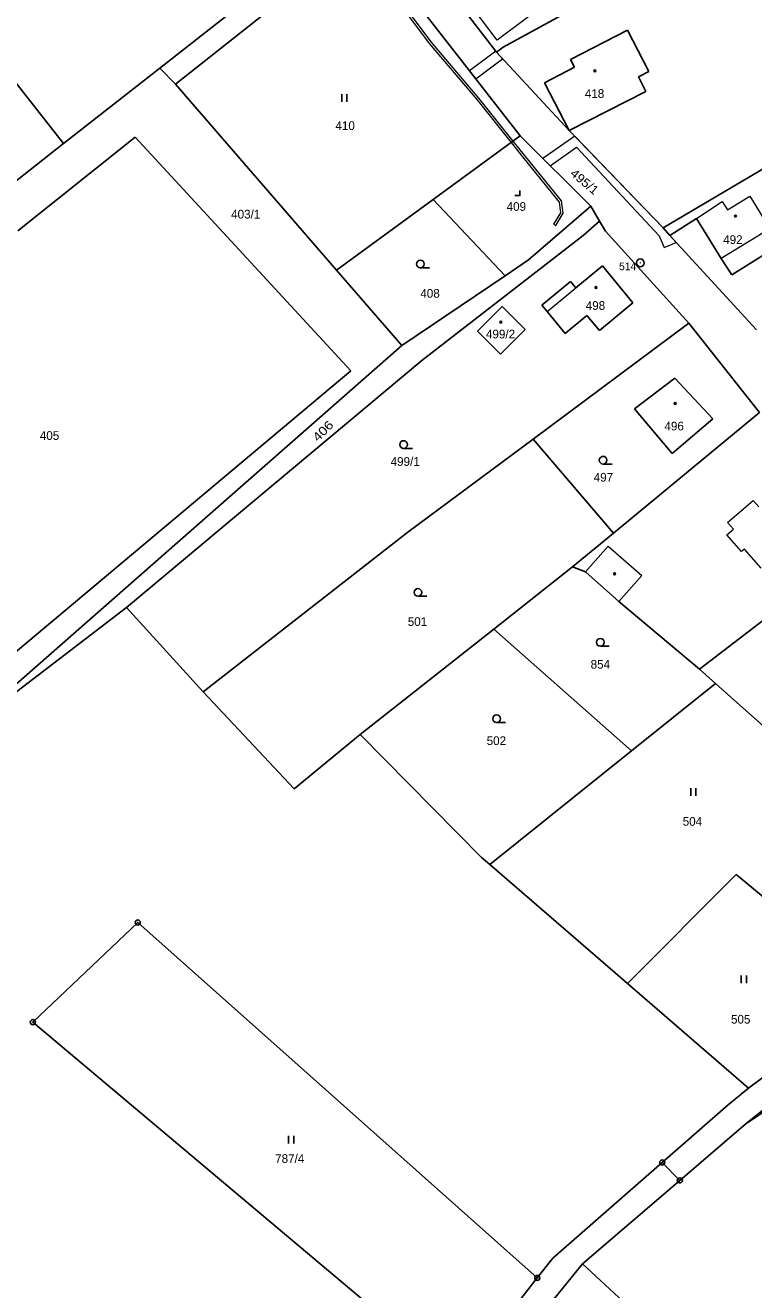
# Model space of a CAD drawing. Extents: x -727701 to -724405, y -960481 to -957284.
# Drawn here: x -726949 to -726806.8, y -958649.2 to -958402.3 of the extents above; entities that cross this region are included whole.
import ezdxf
from ezdxf.enums import TextEntityAlignment as Align

# ---------------------------------------------------------------- set-up
doc = ezdxf.new("R2010")
doc.units = 0
doc.header["$LTSCALE"] = 0.68
for name, color, linetype, lineweight in [('1', 7, 'Continuous', 25), ('13', 7, 'Continuous', 13), ('3', 7, 'Continuous', 25), ('4', 7, 'Continuous', 13), ('5', 7, 'Continuous', 25), ('8', 7, 'Continuous', 25)]:
    doc.layers.add(name, color=color, linetype=linetype, lineweight=lineweight)
doc.layers.add('2', color=7, linetype='Continuous')

msp = doc.modelspace()

# ---------------------------------------------------------------- linework, layer by layer
at = {"layer": '1'}
for p, q in [((-726885.47, -958381.37), (-726922.74, -958410.62)), ((-726974.6, -958383.32), (-726941.54, -958425.38)), ((-726919.69, -958413.75), (-726882.93, -958384.54)), ((-726882.93, -958384.54), (-726852.38, -958423.88)), ((-726869.9, -958390.7), (-726857, -958407.5)), ((-726855.71, -958406.56), (-726838.78, -958397.26)), ((-726842.54, -958408.92), (-726831.41, -958403.2)), ((-726827.24, -958411.31), (-726831.41, -958403.2)), ((-726857, -958407.5), (-726855.71, -958406.56)), ((-726857, -958407.5), (-726842.78, -958422.8)), ((-726841.75, -958410.45), (-726842.54, -958408.92)), ((-726922.74, -958410.62), (-726941.54, -958425.38)), ((-726919.69, -958413.75), (-726922.74, -958410.62)), ((-726847.61, -958413.5), (-726841.75, -958410.45)), ((-726829.26, -958412.35), (-726827.24, -958411.31)), ((-726827.81, -958415.17), (-726829.26, -958412.35)), ((-726888.22, -958450.06), (-726919.69, -958413.75)), ((-726842.78, -958422.8), (-726847.61, -958413.5)), ((-726842.78, -958422.8), (-726827.81, -958415.17)), ((-726950.5, -958442.38), (-726927.59, -958424.09)), ((-726927.59, -958424.09), (-726885.45, -958469.72)), ((-726869.34, -958436.27), (-726852.38, -958423.88)), ((-726852.38, -958423.88), (-726838.54, -958437.62)), ((-726842.78, -958422.8), (-726824.46, -958441.82)), ((-726941.54, -958425.38), (-726955.38, -958436.25)), ((-726824.46, -958441.82), (-726801.69, -958428.42)), ((-726888.22, -958450.06), (-726869.34, -958436.27)), ((-726869.34, -958436.27), (-726855.32, -958451.17)), ((-726850.77, -958448.09), (-726838.54, -958437.62)), ((-726838.54, -958437.62), (-726836.88, -958440.5)), ((-726840.04, -958443.34), (-726836.88, -958440.5)), ((-726836.88, -958440.5), (-726835.73, -958442.5)), ((-726824.46, -958441.82), (-726823.11, -958443.32)), ((-726823.11, -958443.32), (-726817.95, -958439.97)), ((-726813.08, -958447.79), (-726817.95, -958439.97)), ((-726811.04, -958451.01), (-726794.03, -958440.35)), ((-726871.56, -958467.73), (-726840.04, -958443.34)), ((-726835.73, -958442.5), (-726819.45, -958460.45)), ((-726823.11, -958443.32), (-726806.2, -958461.75)), ((-726855.32, -958451.17), (-726850.77, -958448.09)), ((-726841.52, -958453.57), (-726836.29, -958449.26)), ((-726836.29, -958449.26), (-726830.34, -958456.48)), ((-726813.08, -958447.79), (-726811.04, -958451.01)), ((-726875.45, -958464.8), (-726888.22, -958450.06)), ((-726875.45, -958464.8), (-726855.32, -958451.17)), ((-726848.15, -958456.92), (-726842.56, -958452.31)), ((-726842.56, -958452.31), (-726841.52, -958453.57)), ((-726847.11, -958458.18), (-726848.15, -958456.92)), ((-726830.34, -958456.48), (-726836.9, -958461.88)), ((-726860.67, -958462.03), (-726855.87, -958457.21)), ((-726855.87, -958457.21), (-726851.37, -958461.7)), ((-726843.59, -958462.45), (-726847.11, -958458.18)), ((-726839.32, -958458.94), (-726843.59, -958462.45)), ((-726836.9, -958461.88), (-726839.32, -958458.94)), ((-726851.37, -958461.7), (-726856.18, -958466.52)), ((-726849.85, -958483.1), (-726819.45, -958460.45)), ((-726819.45, -958460.45), (-726805.6, -958477.88)), ((-726856.18, -958466.52), (-726860.67, -958462.03)), ((-726875.45, -958464.8), (-726958.11, -958537.36)), ((-726871.56, -958467.73), (-726929.23, -958515.98)), ((-726885.45, -958469.72), (-726961.43, -958533.5)), ((-726830.04, -958477.2), (-726822.14, -958471.2)), ((-726822.14, -958471.2), (-726814.77, -958479.09)), ((-726805.6, -958477.88), (-726834.13, -958501.42)), ((-726822.7, -958485.92), (-726830.04, -958477.2)), ((-726814.77, -958479.09), (-726822.7, -958485.92)), ((-726874.3, -958501.25), (-726849.85, -958483.1)), ((-726849.85, -958483.1), (-726834.13, -958501.42)), ((-726914.29, -958532.43), (-726874.3, -958501.25)), ((-726834.13, -958501.42), (-726842.15, -958508.04)), ((-726783.4, -958501.96), (-726817.37, -958528.01)), ((-726857.54, -958520.18), (-726842.15, -958508.04)), ((-726842.15, -958508.04), (-726839.64, -958509.03)), ((-726839.64, -958509.03), (-726833.08, -958514.79)), ((-726964.44, -958542.91), (-726929.23, -958515.98)), ((-726914.29, -958532.43), (-726929.23, -958515.98)), ((-726833.08, -958514.79), (-726817.37, -958528.01)), ((-726883.62, -958540.76), (-726857.54, -958520.18)), ((-726857.54, -958520.18), (-726830.63, -958543.98)), ((-726814.19, -958530.83), (-726817.37, -958528.01)), ((-726830.63, -958543.98), (-726814.19, -958530.83)), ((-726801.26, -958542.32), (-726814.19, -958530.83)), ((-726896.5, -958551.4), (-726914.29, -958532.43)), ((-726883.62, -958540.76), (-726896.5, -958551.4)), ((-726859.96, -958564.72), (-726883.62, -958540.76)), ((-726858.32, -958566.14), (-726830.63, -958543.98)), ((-726859.96, -958564.72), (-726858.32, -958566.14)), ((-726858.32, -958566.14), (-726831.42, -958589.38)), ((-726810.2, -958568.1), (-726831.42, -958589.38)), ((-726810.2, -958568.1), (-726782.56, -958590.97)), ((-726927.06, -958577.48), (-726947.54, -958596.95)), ((-726849.02, -958646.89), (-726927.06, -958577.48)), ((-726831.42, -958589.38), (-726807.78, -958609.8)), ((-726782.56, -958590.97), (-726807.78, -958609.8)), ((-726778.4, -958592.89), (-726808.24, -958616.76)), ((-726947.54, -958596.95), (-726864.59, -958666.66)), ((-726808.24, -958616.76), (-726791.12, -958605.31)), ((-726807.78, -958609.8), (-726811.76, -958613.11)), ((-726811.76, -958613.11), (-726824.62, -958624.35)), ((-726821.18, -958627.84), (-726808.24, -958616.76)), ((-726845.96, -958643.01), (-726824.62, -958624.35)), ((-726824.62, -958624.35), (-726821.18, -958627.84)), ((-726821.18, -958627.84), (-726840.21, -958644.12)), ((-726886.94, -958701.8), (-726840.21, -958644.12)), ((-726849.02, -958646.89), (-726845.96, -958643.01)), ((-726840.21, -958644.12), (-726776.59, -958702.84)), ((-726864.59, -958666.66), (-726849.02, -958646.89))]:
    msp.add_line(p, q, dxfattribs=at)
at = {"layer": '13'}
msp.add_lwpolyline([(-726878.41, -958394.68), (-726870.15, -958405.83), (-726860.81, -958416.79), (-726854.15, -958425.18), (-726853.75, -958424.88), (-726860.42, -958416.47), (-726869.76, -958405.52), (-726878.03, -958394.36)], dxfattribs=at)
for points in [[(-726862.27, -958411.14), (-726861.05, -958412.72), (-726855.8, -958408.79), (-726857, -958407.5), (-726857.15, -958407.3)], [(-726853.75, -958424.88), (-726854.15, -958425.18), (-726851.94, -958427.97), (-726844.78, -958436.78), (-726844.48, -958438.87), (-726845.85, -958441.08), (-726845.42, -958441.34), (-726843.96, -958438.98), (-726844.31, -958436.57), (-726851.55, -958427.65)], [(-726847.93, -958428.29), (-726846.49, -958429.72), (-726841.34, -958426.1), (-726825.22, -958443.39), (-726824.27, -958445.66), (-726821.88, -958444.66), (-726823.11, -958443.32), (-726824.46, -958441.82), (-726841.71, -958423.91)]]:
    msp.add_lwpolyline(points, close=True, dxfattribs=at)
at = {"layer": '3'}
for p, q in [((-726887.201, -958417.19), (-726887.201, -958415.69)), ((-726886.2, -958417.19), (-726886.2, -958415.69)), ((-726871.853, -958449.64), (-726870.103, -958449.64)), ((-726875.143, -958484.89), (-726873.393, -958484.89)), ((-726836.173, -958487.95), (-726834.423, -958487.95)), ((-726872.343, -958513.77), (-726870.593, -958513.77)), ((-726836.703, -958523.51), (-726834.953, -958523.51)), ((-726856.973, -958538.43), (-726855.223, -958538.43)), ((-726819.041, -958552.75), (-726819.041, -958551.25)), ((-726818.04, -958552.75), (-726818.04, -958551.25)), ((-726809.181, -958589.35), (-726809.181, -958587.85)), ((-726808.18, -958589.35), (-726808.18, -958587.85)), ((-726897.591, -958620.62), (-726897.591, -958619.12)), ((-726896.59, -958620.62), (-726896.59, -958619.12))]:
    msp.add_line(p, q, dxfattribs=at)
msp.add_lwpolyline([(-726853.431, -958435.52), (-726852.43, -958435.52), (-726852.43, -958434.52)], dxfattribs=at)
for centre in [(-726871.8529, -958448.8898), (-726875.1429, -958484.1398), (-726836.1729, -958487.1998), (-726872.3429, -958513.0198), (-726836.7029, -958522.7598), (-726856.9729, -958537.6798)]:
    msp.add_circle(centre, 0.75, dxfattribs=at)
at = {"layer": '4'}
for p, q in [((-726856.84, -958405.19), (-726865.4, -958393.89)), ((-726846.05, -958397.05), (-726856.84, -958405.19)), ((-726817.95, -958439.97), (-726812.91, -958436.69)), ((-726812.91, -958436.69), (-726811.88, -958438.34)), ((-726811.88, -958438.34), (-726807.53, -958435.64)), ((-726807.53, -958435.64), (-726803.59, -958441.99)), ((-726803.59, -958441.99), (-726813.08, -958447.79)), ((-726847.11, -958458.18), (-726841.52, -958453.57)), ((-726811.86, -958499.39), (-726806.86, -958495.05)), ((-726806.86, -958495.05), (-726805.76, -958496.31)), ((-726811.98, -958501.78), (-726810.73, -958500.69)), ((-726810.73, -958500.69), (-726811.86, -958499.39)), ((-726809.11, -958505.04), (-726811.98, -958501.78)), ((-726839.64, -958509.03), (-726835.19, -958503.96)), ((-726835.19, -958503.96), (-726828.63, -958509.72)), ((-726808.55, -958504.56), (-726809.11, -958505.04)), ((-726805.3, -958508.27), (-726808.55, -958504.56)), ((-726828.63, -958509.72), (-726833.08, -958514.79))]:
    msp.add_line(p, q, dxfattribs=at)
at = {"layer": '5'}
for centre in [(-726837.7868, -958411.1592), (-726810.3168, -958439.5292), (-726837.5768, -958453.4792), (-726856.1468, -958460.2492), (-726822.0868, -958476.1192), (-726833.9268, -958509.3792)]:
    msp.add_circle(centre, 0.175, dxfattribs=at)
at = {"layer": '8'}
for centre, radius in [((-726828.89, -958448.6598), 0.75), ((-726828.89, -958448.6598), 0.03), ((-726927.06, -958577.4799), 0.5), ((-726927.06, -958577.4799), 0.0303), ((-726947.54, -958596.9499), 0.5), ((-726947.54, -958596.9499), 0.0303), ((-726824.62, -958624.3499), 0.5), ((-726824.62, -958624.3499), 0.0303), ((-726821.18, -958627.8399), 0.5), ((-726821.18, -958627.8399), 0.0303), ((-726849.02, -958646.8899), 0.5), ((-726849.02, -958646.8899), 0.0303)]:
    msp.add_circle(centre, radius, dxfattribs=at)

# ---------------------------------------------------------------- texts
at = {"layer": '2'}
for s, p in [('418', (-726839.74, -958416.455)), ('410', (-726888.45, -958422.715)), ('409', (-726855.01, -958438.505)), ('492', (-726812.72, -958444.975)), ('408', (-726871.86, -958455.465)), ('498', (-726839.56, -958457.845)), ('405', (-726946.18, -958483.235)), ('496', (-726824.19, -958481.385)), ('497', (-726838.01, -958491.385)), ('501', (-726874.32, -958519.565)), ('502', (-726858.91, -958542.825)), ('504', (-726820.62, -958558.585)), ('505', (-726811.19, -958597.225)), ('787/4', (-726900.22, -958624.435))]:
    msp.add_text(s, height=1.7, dxfattribs=at).set_placement(p)
for s, rotation, width, p in [('495/1', 320, 1.1, (-726842.733, -958431.455)), ('406', 45, 1.2, (-726891.889, -958483.7))]:
    msp.add_text(s, height=1.7, rotation=rotation, dxfattribs=dict(at, width=width)).set_placement(p)
for s, p in [('403/1', (-726905.97, -958440.005)), ('499/2', (-726856.2, -958463.415)), ('499/1', (-726874.82, -958488.305)), ('854', (-726836.709, -958527.905))]:
    msp.add_text(s, height=1.7, dxfattribs=at).set_placement(p, align=Align.CENTER)
at = {"layer": '8'}
msp.add_text('514', height=1.5, dxfattribs=at).set_placement((-726833.06, -958450.095))

doc.saveas('drawing.dxf')
